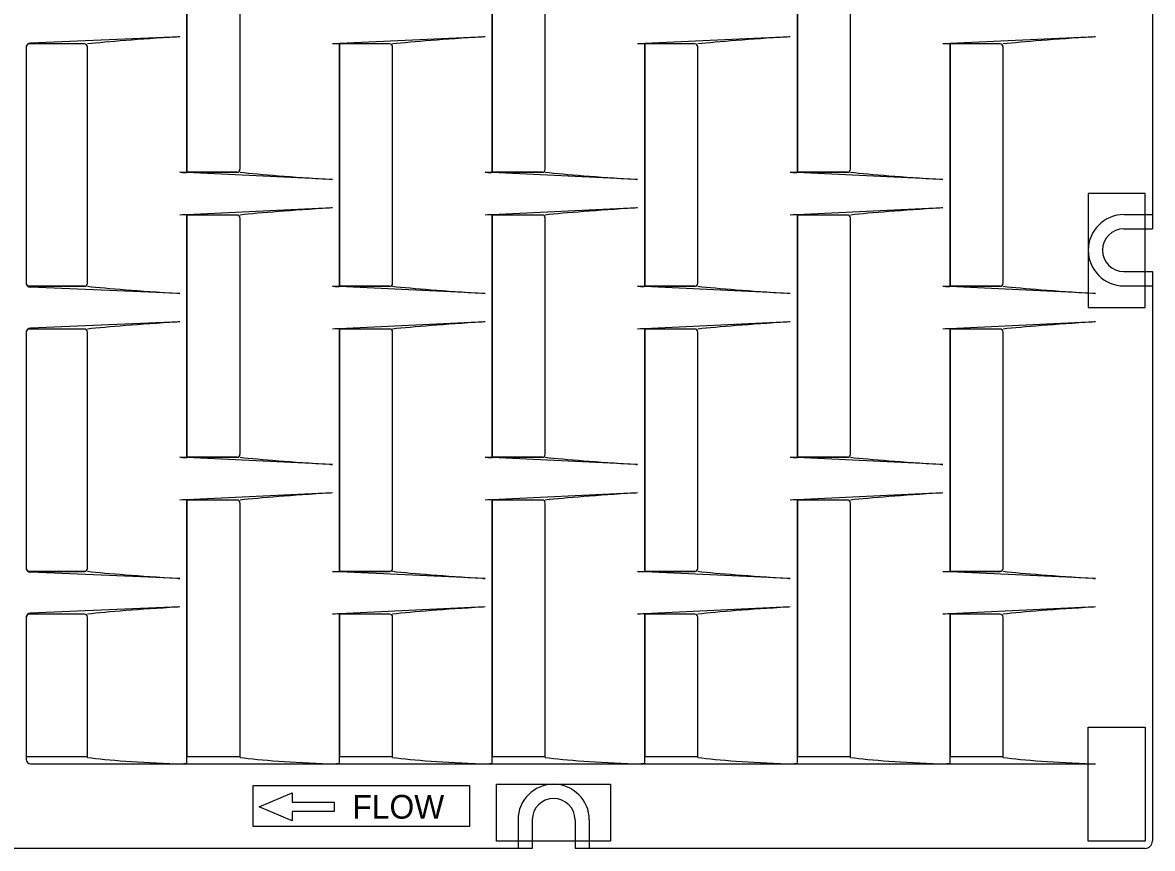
# Model space of a CAD drawing. Extents: x 99862 to 103151, y 100000 to 102076.
# Drawn here: x 100116.3 to 100512.9, y 101577.7 to 101867.6 of the extents above; entities that cross this region are included whole.
import ezdxf

# ---------------------------------------------------------------- set-up
doc = ezdxf.new("R2010")
doc.units = 0
for name, color, linetype in [('Level 10', 7, 'Continuous'), ('Level 11', 7, 'Continuous'), ('Level 2', 7, 'Continuous'), ('Level 20', 7, 'Continuous')]:
    doc.layers.add(name, color=color, linetype=linetype)

msp = doc.modelspace()

# ---------------------------------------------------------------- linework, layer by layer
at = {"layer": 'Level 10'}
for points in [[(100173.97, 101900.12), (100173.97, 101815.06), (100191.55, 101815.06)], [(100281.11, 101900.12), (100281.11, 101815.06), (100298.69, 101815.06)], [(100388.25, 101900.12), (100388.25, 101815.06), (100405.84, 101815.06)], [(100192.6, 101816.1), (100192.6, 101899.08)], [(100299.74, 101816.1), (100299.74, 101899.08)], [(100406.88, 101816.1), (100406.88, 101899.08)], [(100117.53, 101858.82), (100117.53, 101776.3)], [(100137.98, 101860.09), (100118.18, 101860.09)], [(100139.02, 101776.07), (100139.02, 101859.05)], [(100227.54, 101860.09), (100227.54, 101775.03), (100245.12, 101775.03)], [(100245.12, 101860.09), (100227.54, 101860.09)], [(100246.17, 101776.07), (100246.17, 101859.05)], [(100334.68, 101860.09), (100334.68, 101775.03), (100352.27, 101775.03)], [(100352.27, 101860.09), (100334.68, 101860.09)], [(100353.31, 101776.07), (100353.31, 101859.05)], [(100441.82, 101860.09), (100441.82, 101775.03), (100459.41, 101775.03)], [(100459.41, 101860.09), (100441.82, 101860.09)], [(100460.45, 101776.07), (100460.45, 101859.05)], [(100173.97, 101800.05), (100173.97, 101714.98), (100191.55, 101714.98)], [(100191.55, 101800.05), (100173.97, 101800.05)], [(100192.6, 101716.03), (100192.6, 101799)], [(100281.11, 101800.05), (100281.11, 101714.98), (100298.69, 101714.98)], [(100298.69, 101800.05), (100281.11, 101800.05)], [(100299.74, 101716.03), (100299.74, 101799)], [(100388.25, 101800.05), (100388.25, 101714.98), (100405.84, 101714.98)], [(100405.84, 101800.05), (100388.25, 101800.05)], [(100406.88, 101716.03), (100406.88, 101799)], [(100118.18, 101775.03), (100137.98, 101775.03)], [(100117.53, 101758.75), (100117.53, 101676.22)], [(100137.98, 101760.02), (100118.18, 101760.02)], [(100139.02, 101676), (100139.02, 101758.97)], [(100227.54, 101760.02), (100227.54, 101674.95), (100245.12, 101674.95)], [(100245.12, 101760.02), (100227.54, 101760.02)], [(100246.17, 101676), (100246.17, 101758.97)], [(100334.68, 101760.02), (100334.68, 101674.95), (100352.27, 101674.95)], [(100352.27, 101760.02), (100334.68, 101760.02)], [(100353.31, 101676), (100353.31, 101758.97)], [(100441.82, 101760.02), (100441.82, 101674.95), (100459.41, 101674.95)], [(100459.41, 101760.02), (100441.82, 101760.02)], [(100460.45, 101676), (100460.45, 101758.97)], [(100173.97, 101699.97), (100173.97, 101609.9), (100192.6, 101609.9), (100192.6, 101698.93)], [(100191.55, 101699.97), (100173.97, 101699.97)], [(100281.11, 101699.97), (100281.11, 101609.9), (100299.74, 101609.9), (100299.74, 101698.93)], [(100298.69, 101699.97), (100281.11, 101699.97)], [(100388.25, 101699.97), (100388.25, 101609.9), (100406.88, 101609.9), (100406.88, 101698.93)], [(100405.84, 101699.97), (100388.25, 101699.97)], [(100118.18, 101674.95), (100137.98, 101674.95)], [(100117.53, 101658.67), (100117.53, 101609.9), (100139.02, 101609.9), (100139.02, 101616.46), (100139.02, 101658.9)], [(100137.98, 101659.94), (100118.18, 101659.94)], [(100227.54, 101659.94), (100227.54, 101609.9), (100246.17, 101609.9), (100246.17, 101658.9)], [(100245.12, 101659.94), (100227.54, 101659.94)], [(100334.68, 101659.94), (100334.68, 101609.9), (100353.31, 101609.9), (100353.31, 101658.9)], [(100352.27, 101659.94), (100334.68, 101659.94)], [(100441.82, 101659.94), (100441.82, 101609.9), (100460.45, 101609.9), (100460.45, 101658.9)], [(100459.41, 101659.94), (100441.82, 101659.94)]]:
    msp.add_lwpolyline(points, dxfattribs=at)
for centre, radius, start, end in [((100119.09, 101858.82), 1.57, 125.8762, 180), ((100137.98, 101859.05), 1.04, 360, 90), ((100245.12, 101859.05), 1.04, 360, 90), ((100352.27, 101859.05), 1.04, 360, 90), ((100459.41, 101859.05), 1.04, 360, 90), ((100191.55, 101816.1), 1.04, 270, 0), ((100298.69, 101816.1), 1.04, 270, 0), ((100405.84, 101816.1), 1.04, 270, 0), ((100191.55, 101799), 1.04, 360, 90), ((100298.69, 101799), 1.04, 360, 90), ((100405.84, 101799), 1.04, 360, 90), ((100119.09, 101776.3), 1.57, 180, 234.1238), ((100137.98, 101776.07), 1.04, 270, 0), ((100245.12, 101776.07), 1.04, 270, 0), ((100352.27, 101776.07), 1.04, 270, 0), ((100459.41, 101776.07), 1.04, 270, 0), ((100119.09, 101758.75), 1.57, 125.8762, 180), ((100137.98, 101758.97), 1.04, 360, 90), ((100245.12, 101758.97), 1.04, 360, 90), ((100352.27, 101758.97), 1.04, 360, 90), ((100459.41, 101758.97), 1.04, 360, 90), ((100191.55, 101716.03), 1.04, 270, 0), ((100298.69, 101716.03), 1.04, 270, 0), ((100405.84, 101716.03), 1.04, 270, 0), ((100191.55, 101698.93), 1.04, 360, 90), ((100298.69, 101698.93), 1.04, 360, 90), ((100405.84, 101698.93), 1.04, 360, 90), ((100119.09, 101676.22), 1.57, 180, 234.1238), ((100137.98, 101676), 1.04, 270, 0), ((100245.12, 101676), 1.04, 270, 0), ((100352.27, 101676), 1.04, 270, 0), ((100459.41, 101676), 1.04, 270, 0), ((100119.09, 101658.67), 1.57, 125.8762, 180), ((100137.98, 101658.9), 1.04, 0, 90), ((100245.12, 101658.9), 1.04, 360, 90), ((100352.27, 101658.9), 1.04, 360, 90), ((100459.41, 101658.9), 1.04, 360, 90)]:
    msp.add_arc(centre, radius, start, end, dxfattribs=at)
at = {"layer": 'Level 11'}
for p, q in [((100502.86, 101800.19), (100512.87, 101800.19)), ((100502.86, 101795.19), (100512.87, 101795.19)), ((100502.86, 101780.18), (100512.87, 101780.18)), ((100502.86, 101775.18), (100512.87, 101775.18)), ((100290.18, 101587.69), (100290.18, 101577.68)), ((100295.18, 101587.69), (100295.18, 101577.68)), ((100310.19, 101587.69), (100310.19, 101577.68)), ((100315.2, 101587.69), (100315.2, 101577.68))]:
    msp.add_line(p, q, dxfattribs=at)
for points in [[(100510.37, 101807.55), (100490.35, 101807.55), (100490.35, 101767.52), (100510.37, 101767.52)], [(100510.37, 101580.18), (100490.35, 101580.18), (100490.35, 101620.21), (100510.37, 101620.21)], [(100197.06, 101599.64), (100197.06, 101585.45), (100273.27, 101585.45), (100273.27, 101599.64)], [(100322.7, 101600.2), (100322.7, 101580.18), (100282.67, 101580.18), (100282.67, 101600.2)]]:
    msp.add_lwpolyline(points, close=True, dxfattribs=at)
msp.add_lwpolyline([(100210.85, 101597.22), (100210.85, 101593.94), (100225.63, 101593.94), (100225.63, 101590.65), (100210.85, 101590.65), (100210.85, 101587.37), (100199.36, 101592.3), (100210.85, 101597.22)], dxfattribs=at)
for centre, radius, start, end in [((100502.86, 101787.68), 12.51, 90, 270), ((100502.86, 101787.68), 7.51, 90, 270), ((100302.69, 101587.69), 12.51, 360, 180), ((100302.69, 101587.69), 7.51, 360, 180)]:
    msp.add_arc(centre, radius, start, end, dxfattribs=at)
at = {"layer": 'Level 2'}
for p, q in [((100512.87, 101995.08), (100512.87, 101795.19)), ((100173.97, 101815.03), (100173.97, 101900.14)), ((100281.11, 101815.03), (100281.11, 101900.14)), ((100388.25, 101815.03), (100388.25, 101900.14)), ((100192.6, 101816.1), (100192.6, 101899.08)), ((100299.74, 101816.1), (100299.74, 101899.08)), ((100406.88, 101816.1), (100406.88, 101899.08)), ((100171.47, 101862.59), (100119.02, 101860.39)), ((100278.61, 101862.59), (100225.04, 101860.09)), ((100385.75, 101862.59), (100332.18, 101860.09)), ((100492.89, 101862.59), (100439.32, 101860.09)), ((100117.53, 101858.82), (100117.53, 101776.3)), ((100137.98, 101860.09), (100118.18, 101860.09)), ((100139.02, 101776.07), (100139.02, 101859.05)), ((100227.54, 101775), (100227.54, 101860.12)), ((100245.12, 101860.09), (100227.54, 101860.09)), ((100246.17, 101776.07), (100246.17, 101859.05)), ((100334.68, 101775), (100334.68, 101860.12)), ((100352.27, 101860.09), (100334.68, 101860.09)), ((100353.31, 101776.07), (100353.31, 101859.05)), ((100441.82, 101775), (100441.82, 101860.12)), ((100459.41, 101860.09), (100441.82, 101860.09)), ((100460.45, 101776.07), (100460.45, 101859.05)), ((100225.04, 101812.56), (100171.47, 101815.06)), ((100191.55, 101815.06), (100173.97, 101815.06)), ((100332.18, 101812.56), (100278.61, 101815.06)), ((100298.69, 101815.06), (100281.11, 101815.06)), ((100439.32, 101812.56), (100385.75, 101815.06)), ((100405.84, 101815.06), (100388.25, 101815.06)), ((100225.04, 101802.55), (100171.47, 101800.05)), ((100332.18, 101802.55), (100278.61, 101800.05)), ((100439.32, 101802.55), (100385.75, 101800.05)), ((100173.97, 101714.96), (100173.97, 101800.07)), ((100191.55, 101800.05), (100173.97, 101800.05)), ((100192.6, 101716.03), (100192.6, 101799)), ((100281.11, 101714.96), (100281.11, 101800.07)), ((100298.69, 101800.05), (100281.11, 101800.05)), ((100299.74, 101716.03), (100299.74, 101799)), ((100388.25, 101714.96), (100388.25, 101800.07)), ((100405.84, 101800.05), (100388.25, 101800.05)), ((100406.88, 101716.03), (100406.88, 101799)), ((100512.87, 101780.18), (100512.87, 101580.29)), ((100137.98, 101775.03), (100118.18, 101775.03)), ((100171.47, 101772.53), (100119.02, 101774.73)), ((100278.61, 101772.53), (100225.04, 101775.03)), ((100245.12, 101775.03), (100227.54, 101775.03)), ((100385.75, 101772.53), (100332.18, 101775.03)), ((100352.27, 101775.03), (100334.68, 101775.03)), ((100492.89, 101772.53), (100439.32, 101775.03)), ((100459.41, 101775.03), (100441.82, 101775.03)), ((100171.47, 101762.52), (100119.02, 101760.31)), ((100278.61, 101762.52), (100225.04, 101760.02)), ((100385.75, 101762.52), (100332.18, 101760.02)), ((100492.89, 101762.52), (100439.32, 101760.02)), ((100117.53, 101758.75), (100117.53, 101676.22)), ((100137.98, 101760.02), (100118.18, 101760.02)), ((100139.02, 101676), (100139.02, 101758.97)), ((100227.54, 101674.93), (100227.54, 101760.04)), ((100245.12, 101760.02), (100227.54, 101760.02)), ((100246.17, 101676), (100246.17, 101758.97)), ((100334.68, 101674.93), (100334.68, 101760.04)), ((100352.27, 101760.02), (100334.68, 101760.02)), ((100353.31, 101676), (100353.31, 101758.97)), ((100441.82, 101674.93), (100441.82, 101760.04)), ((100459.41, 101760.02), (100441.82, 101760.02)), ((100460.45, 101676), (100460.45, 101758.97)), ((100225.04, 101712.48), (100171.47, 101714.98)), ((100191.55, 101714.98), (100173.97, 101714.98)), ((100332.18, 101712.48), (100278.61, 101714.98)), ((100298.69, 101714.98), (100281.11, 101714.98)), ((100439.32, 101712.48), (100385.75, 101714.98)), ((100405.84, 101714.98), (100388.25, 101714.98)), ((100225.04, 101702.47), (100171.47, 101699.97)), ((100332.18, 101702.47), (100278.61, 101699.97)), ((100439.32, 101702.47), (100385.75, 101699.97)), ((100173.97, 101607.6), (100173.97, 101700)), ((100191.55, 101699.97), (100173.97, 101699.97)), ((100192.6, 101609.9), (100192.6, 101698.93)), ((100281.11, 101607.6), (100281.11, 101700)), ((100298.69, 101699.97), (100281.11, 101699.97)), ((100299.74, 101609.9), (100299.74, 101698.93)), ((100388.25, 101607.6), (100388.25, 101700)), ((100405.84, 101699.97), (100388.25, 101699.97)), ((100406.88, 101609.9), (100406.88, 101698.93)), ((100137.98, 101674.95), (100118.18, 101674.95)), ((100171.47, 101672.45), (100119.02, 101674.66)), ((100278.61, 101672.45), (100225.04, 101674.95)), ((100245.12, 101674.95), (100227.54, 101674.95)), ((100385.75, 101672.45), (100332.18, 101674.95)), ((100352.27, 101674.95), (100334.68, 101674.95)), ((100492.89, 101672.45), (100439.32, 101674.95)), ((100459.41, 101674.95), (100441.82, 101674.95)), ((100171.47, 101662.44), (100119.02, 101660.24)), ((100278.61, 101662.44), (100225.04, 101659.94)), ((100385.75, 101662.44), (100332.18, 101659.94)), ((100492.89, 101662.44), (100439.32, 101659.94)), ((100117.53, 101658.67), (100117.53, 101608.97)), ((100137.98, 101659.94), (100118.18, 101659.94)), ((100139.02, 101616.46), (100139.02, 101658.9)), ((100227.54, 101607.6), (100227.54, 101659.97)), ((100245.12, 101659.94), (100227.54, 101659.94)), ((100246.17, 101609.9), (100246.17, 101658.9)), ((100334.68, 101607.6), (100334.68, 101659.97)), ((100352.27, 101659.94), (100334.68, 101659.94)), ((100353.31, 101609.9), (100353.31, 101658.9)), ((100441.82, 101607.6), (100441.82, 101659.97)), ((100459.41, 101659.94), (100441.82, 101659.94)), ((100460.45, 101609.9), (100460.45, 101658.9)), ((100139.02, 101609.9), (100139.02, 101616.46)), ((100117.53, 101609.9), (100139.02, 101609.9)), ((100119.09, 101607.4), (100492.85, 101607.4)), ((100139.02, 101609.61), (100139.02, 101609.9)), ((100173.97, 101609.9), (100192.6, 101609.9)), ((100192.6, 101609.61), (100192.6, 101609.9)), ((100227.54, 101609.9), (100246.17, 101609.9)), ((100246.17, 101609.61), (100246.17, 101609.9)), ((100281.11, 101609.9), (100299.74, 101609.9)), ((100299.74, 101609.61), (100299.74, 101609.9)), ((100334.68, 101609.9), (100353.31, 101609.9)), ((100353.31, 101609.61), (100353.31, 101609.9)), ((100388.25, 101609.9), (100406.88, 101609.9)), ((100406.88, 101609.61), (100406.88, 101609.9)), ((100441.82, 101609.9), (100460.45, 101609.9)), ((100460.45, 101609.61), (100460.45, 101609.9)), ((100295.18, 101577.68), (100095.12, 101577.68)), ((100510.26, 101577.68), (100310.19, 101577.68))]:
    msp.add_line(p, q, dxfattribs=at)
for centre, radius, start, end in [((100119.09, 101858.82), 1.57, 92.6026, 180), ((100137.98, 101859.05), 1.04, 0, 90), ((100245.12, 101859.05), 1.04, 0, 90), ((100352.27, 101859.05), 1.04, 0, 90), ((100459.41, 101859.05), 1.04, 0, 90), ((100191.55, 101816.1), 1.04, 270, 0), ((100298.69, 101816.1), 1.04, 270, 0), ((100405.84, 101816.1), 1.04, 270, 0), ((100191.55, 101799), 1.04, 0, 90), ((100298.69, 101799), 1.04, 0, 90), ((100405.84, 101799), 1.04, 0, 90), ((100119.09, 101776.3), 1.57, 180, 267.3974), ((100137.98, 101776.07), 1.04, 270, 0), ((100245.12, 101776.07), 1.04, 270, 0), ((100352.27, 101776.07), 1.04, 270, 0), ((100459.41, 101776.07), 1.04, 270, 0), ((100119.09, 101758.75), 1.57, 92.6026, 180), ((100137.98, 101758.97), 1.04, 0, 90), ((100245.12, 101758.97), 1.04, 0, 90), ((100352.27, 101758.97), 1.04, 0, 90), ((100459.41, 101758.97), 1.04, 0, 90), ((100191.55, 101716.03), 1.04, 270, 0), ((100298.69, 101716.03), 1.04, 270, 0), ((100405.84, 101716.03), 1.04, 270, 0), ((100191.55, 101698.93), 1.04, 0, 90), ((100298.69, 101698.93), 1.04, 0, 90), ((100405.84, 101698.93), 1.04, 0, 90), ((100119.09, 101676.22), 1.57, 180, 267.3974), ((100137.98, 101676), 1.04, 270, 0), ((100245.12, 101676), 1.04, 270, 0), ((100352.27, 101676), 1.04, 270, 0), ((100459.41, 101676), 1.04, 270, 0), ((100119.09, 101658.67), 1.57, 92.6026, 180), ((100137.98, 101658.9), 1.04, 0, 90), ((100245.12, 101658.9), 1.04, 0, 90), ((100352.27, 101658.9), 1.04, 0, 90), ((100459.41, 101658.9), 1.04, 0, 90), ((100119.09, 101608.97), 1.57, 180, 270), ((100510.26, 101580.29), 2.61, 270, 0)]:
    msp.add_arc(centre, radius, start, end, dxfattribs=at)
for centre, major_axis, ratio, start_param, end_param in [((100199.55, 101861.58), (70.05, 3.19), 0.035758, 1.997966, 2.612379), ((100171.47, 101862.5), (2.5, 0.11), 0.035758, 1.569169, 1.997966), ((100225.04, 101860), (2.5, 0.11), 0.035758, 6.281558, 7.852354), ((100306.69, 101861.58), (70.05, 3.19), 0.035758, 1.997966, 2.612379), ((100278.61, 101862.5), (2.5, 0.11), 0.035758, 1.569169, 1.997966), ((100332.18, 101860), (2.5, 0.11), 0.035758, 6.281558, 7.852354), ((100413.84, 101861.58), (70.05, 3.19), 0.035758, 1.997966, 2.612379), ((100385.75, 101862.5), (2.5, 0.11), 0.035758, 1.569169, 1.997966), ((100439.32, 101860), (2.5, 0.11), 0.035758, 6.281558, 7.852354), ((100520.98, 101861.58), (70.05, 3.19), 0.035758, 1.997966, 2.612379), ((100492.89, 101862.5), (2.5, 0.11), 0.035758, 1.569169, 1.997966), ((100171.47, 101815.15), (-2.5, 0.11), 0.035758, 1.572424, 3.14322), ((100253.12, 101813.57), (-70.05, 3.19), 0.035758, 0.529214, 1.143627), ((100225.04, 101812.65), (-2.5, 0.11), 0.035758, 1.143627, 1.572424), ((100278.61, 101815.15), (-2.5, 0.11), 0.035758, 1.572424, 3.14322), ((100360.26, 101813.57), (-70.05, 3.19), 0.035758, 0.529214, 1.143627), ((100332.18, 101812.65), (-2.5, 0.11), 0.035758, 1.143627, 1.572424), ((100385.75, 101815.15), (-2.5, 0.11), 0.035758, 1.572424, 3.14322), ((100467.41, 101813.57), (-70.05, 3.19), 0.035758, 0.529214, 1.143627), ((100439.32, 101812.65), (-2.5, 0.11), 0.035758, 1.143627, 1.572424), ((100253.12, 101801.53), (70.05, 3.19), 0.035758, 1.997966, 2.612379), ((100225.04, 101802.46), (2.5, 0.11), 0.035758, 1.569169, 1.997966), ((100360.26, 101801.53), (70.05, 3.19), 0.035758, 1.997966, 2.612379), ((100332.18, 101802.46), (2.5, 0.11), 0.035758, 1.569169, 1.997966), ((100467.41, 101801.53), (70.05, 3.19), 0.035758, 1.997966, 2.612379), ((100439.32, 101802.46), (2.5, 0.11), 0.035758, 1.569169, 1.997966), ((100171.47, 101799.96), (2.5, 0.11), 0.035758, 6.281558, 7.852354), ((100278.61, 101799.96), (2.5, 0.11), 0.035758, 6.281558, 7.852354), ((100385.75, 101799.96), (2.5, 0.11), 0.035758, 6.281558, 7.852354), ((100199.55, 101773.54), (-70.05, 3.19), 0.035758, 0.529214, 1.143627), ((100225.04, 101775.12), (-2.5, 0.11), 0.035758, 1.572424, 3.14322), ((100306.69, 101773.54), (-70.05, 3.19), 0.035758, 0.529214, 1.143627), ((100332.18, 101775.12), (-2.5, 0.11), 0.035758, 1.572424, 3.14322), ((100413.84, 101773.54), (-70.05, 3.19), 0.035758, 0.529214, 1.143627), ((100439.32, 101775.12), (-2.5, 0.11), 0.035758, 1.572424, 3.14322), ((100520.98, 101773.54), (-70.05, 3.19), 0.035758, 0.529214, 1.143627), ((100171.47, 101772.62), (-2.5, 0.11), 0.035758, 1.143627, 1.572424), ((100278.61, 101772.62), (-2.5, 0.11), 0.035758, 1.143627, 1.572424), ((100385.75, 101772.62), (-2.5, 0.11), 0.035758, 1.143627, 1.572424), ((100492.89, 101772.62), (-2.5, 0.11), 0.035758, 1.143627, 1.572424), ((100199.55, 101761.5), (70.05, 3.19), 0.035758, 1.997966, 2.612379), ((100171.47, 101762.43), (2.5, 0.11), 0.035758, 1.569169, 1.997966), ((100306.69, 101761.5), (70.05, 3.19), 0.035758, 1.997966, 2.612379), ((100278.61, 101762.43), (2.5, 0.11), 0.035758, 1.569169, 1.997966), ((100413.84, 101761.5), (70.05, 3.19), 0.035758, 1.997966, 2.612379), ((100385.75, 101762.43), (2.5, 0.11), 0.035758, 1.569169, 1.997966), ((100520.98, 101761.5), (70.05, 3.19), 0.035758, 1.997966, 2.612379), ((100492.89, 101762.43), (2.5, 0.11), 0.035758, 1.569169, 1.997966), ((100225.04, 101759.93), (2.5, 0.11), 0.035758, 6.281558, 7.852354), ((100332.18, 101759.93), (2.5, 0.11), 0.035758, 6.281558, 7.852354), ((100439.32, 101759.93), (2.5, 0.11), 0.035758, 6.281558, 7.852354), ((100171.47, 101715.07), (-2.5, 0.11), 0.035758, 1.572424, 3.14322), ((100253.12, 101713.5), (-70.05, 3.19), 0.035758, 0.529214, 1.143627), ((100278.61, 101715.07), (-2.5, 0.11), 0.035758, 1.572424, 3.14322), ((100360.26, 101713.5), (-70.05, 3.19), 0.035758, 0.529214, 1.143627), ((100385.75, 101715.07), (-2.5, 0.11), 0.035758, 1.572424, 3.14322), ((100467.41, 101713.5), (-70.05, 3.19), 0.035758, 0.529214, 1.143627), ((100225.04, 101712.57), (-2.5, 0.11), 0.035758, 1.143627, 1.572424), ((100332.18, 101712.57), (-2.5, 0.11), 0.035758, 1.143627, 1.572424), ((100439.32, 101712.57), (-2.5, 0.11), 0.035758, 1.143627, 1.572424), ((100253.12, 101701.46), (70.05, 3.19), 0.035758, 1.997966, 2.612379), ((100225.04, 101702.38), (2.5, 0.11), 0.035758, 1.569169, 1.997966), ((100360.26, 101701.46), (70.05, 3.19), 0.035758, 1.997966, 2.612379), ((100332.18, 101702.38), (2.5, 0.11), 0.035758, 1.569169, 1.997966), ((100467.41, 101701.46), (70.05, 3.19), 0.035758, 1.997966, 2.612379), ((100439.32, 101702.38), (2.5, 0.11), 0.035758, 1.569169, 1.997966), ((100171.47, 101699.88), (2.5, 0.11), 0.035758, 6.281558, 7.852354), ((100278.61, 101699.88), (2.5, 0.11), 0.035758, 6.281558, 7.852354), ((100385.75, 101699.88), (2.5, 0.11), 0.035758, 6.281558, 7.852354), ((100199.55, 101673.47), (-70.05, 3.19), 0.035758, 0.529214, 1.143627), ((100225.04, 101675.04), (-2.5, 0.11), 0.035758, 1.572424, 3.14322), ((100306.69, 101673.47), (-70.05, 3.19), 0.035758, 0.529214, 1.143627), ((100332.18, 101675.04), (-2.5, 0.11), 0.035758, 1.572424, 3.14322), ((100413.84, 101673.47), (-70.05, 3.19), 0.035758, 0.529214, 1.143627), ((100439.32, 101675.04), (-2.5, 0.11), 0.035758, 1.572424, 3.14322), ((100520.98, 101673.47), (-70.05, 3.19), 0.035758, 0.529214, 1.143627), ((100171.47, 101672.54), (-2.5, 0.11), 0.035758, 1.143627, 1.572424), ((100278.61, 101672.54), (-2.5, 0.11), 0.035758, 1.143627, 1.572424), ((100385.75, 101672.54), (-2.5, 0.11), 0.035758, 1.143627, 1.572424), ((100492.89, 101672.54), (-2.5, 0.11), 0.035758, 1.143627, 1.572424), ((100199.55, 101661.43), (70.05, 3.19), 0.035758, 1.997966, 2.612379), ((100171.47, 101662.35), (2.5, 0.11), 0.035758, 1.569169, 1.997966), ((100306.69, 101661.43), (70.05, 3.19), 0.035758, 1.997966, 2.612379), ((100278.61, 101662.35), (2.5, 0.11), 0.035758, 1.569169, 1.997966), ((100413.84, 101661.43), (70.05, 3.19), 0.035758, 1.997966, 2.612379), ((100385.75, 101662.35), (2.5, 0.11), 0.035758, 1.569169, 1.997966), ((100520.98, 101661.43), (70.05, 3.19), 0.035758, 1.997966, 2.612379), ((100492.89, 101662.35), (2.5, 0.11), 0.035758, 1.569169, 1.997966), ((100225.04, 101659.85), (2.5, 0.11), 0.035758, 6.281558, 7.852354), ((100332.18, 101659.85), (2.5, 0.11), 0.035758, 6.281558, 7.852354), ((100439.32, 101659.85), (2.5, 0.11), 0.035758, 6.281558, 7.852354), ((100199.55, 101612.32), (-70.05, 0), 0.076923, 0.527586, 1.142), ((100171.47, 101607.6), (-2.5, 0), 0.076923, 1.142, 1.570796), ((100171.47, 101607.6), (-2.5, 0), 0.076923, 1.570796, 3.141593), ((100253.12, 101612.32), (-70.05, 0), 0.076923, 0.527586, 1.142), ((100225.04, 101607.6), (-2.5, 0), 0.076923, 1.142, 1.570796), ((100225.04, 101607.6), (-2.5, 0), 0.076923, 1.570796, 3.141593), ((100306.69, 101612.32), (-70.05, 0), 0.076923, 0.527586, 1.142), ((100278.61, 101607.6), (-2.5, 0), 0.076923, 1.142, 1.570796), ((100278.61, 101607.6), (-2.5, 0), 0.076923, 1.570796, 3.141593), ((100360.26, 101612.32), (-70.05, 0), 0.076923, 0.527586, 1.142), ((100332.18, 101607.6), (-2.5, 0), 0.076923, 1.142, 1.570796), ((100332.18, 101607.6), (-2.5, 0), 0.076923, 1.570796, 3.141593), ((100413.84, 101612.32), (-70.05, 0), 0.076923, 0.527586, 1.142), ((100385.75, 101607.6), (-2.5, 0), 0.076923, 1.142, 1.570796), ((100385.75, 101607.6), (-2.5, 0), 0.076923, 1.570796, 3.141593), ((100467.41, 101612.32), (-70.05, 0), 0.076923, 0.527586, 1.142), ((100439.32, 101607.6), (-2.5, 0), 0.076923, 1.142, 1.570796), ((100439.32, 101607.6), (-2.5, 0), 0.076923, 1.570796, 3.141593), ((100520.98, 101612.32), (-70.05, 0), 0.076923, 0.527586, 1.142), ((100492.85, 101607.6), (-2.5, 0), 0.076923, 1.142, 1.570796), ((100492.89, 101607.6), (-2.5, 0), 0.076923, 1.142, 1.570796)]:
    msp.add_ellipse(centre, major_axis=major_axis, ratio=ratio, start_param=start_param, end_param=end_param, dxfattribs=at)

# ---------------------------------------------------------------- texts
at = {"layer": 'Level 20'}
msp.add_text('FLOW', height=8.349, dxfattribs=at).set_placement((100232.04, 101588.12))

doc.saveas('drawing.dxf')
